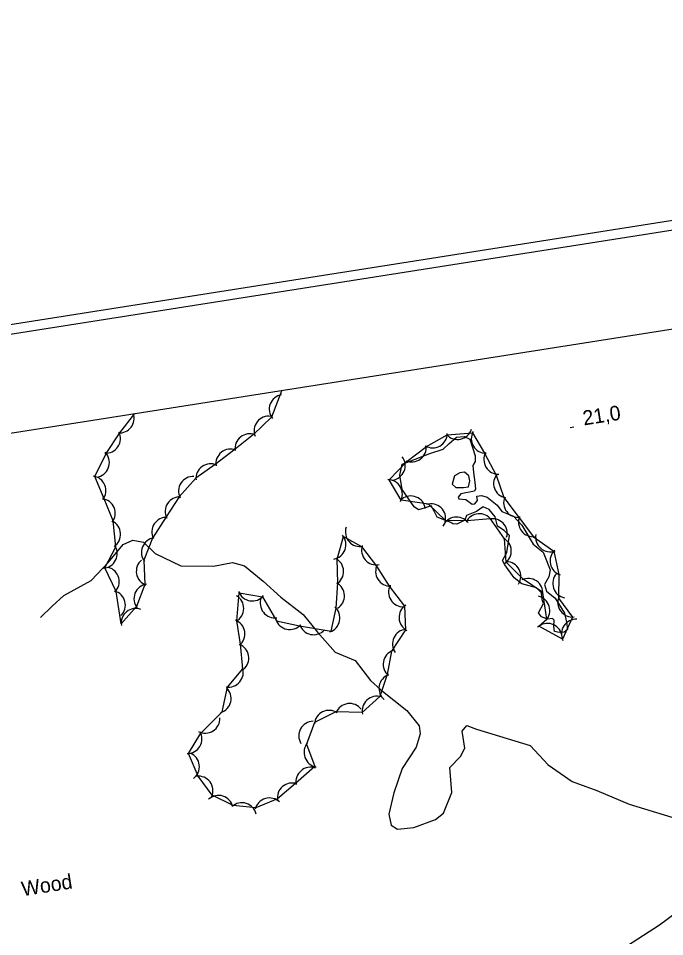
# Model space of a CAD drawing. Extents: x 646142 to 649934, y 5874075 to 5876351.
# Drawn here: x 646416.2 to 646548.7, y 5875715 to 5875903.2 of the extents above; entities that cross this region are included whole.
import ezdxf

# ---------------------------------------------------------------- set-up
doc = ezdxf.new("R2010")
doc.units = 0
for name, color, linetype in [('Niveau 1', 7, 'Continuous'), ('Niveau 3', 7, 'Continuous'), ('Niveau 4', 7, 'Continuous'), ('Niveau 44', 7, 'Continuous'), ('Niveau 60', 7, 'Continuous')]:
    doc.layers.add(name, color=color, linetype=linetype)

msp = doc.modelspace()

# ---------------------------------------------------------------- linework, layer by layer
at = {"layer": 'Niveau 1'}
for points in [[(646420.73, 5875780.37), (646423.1, 5875782.75), (646425.52, 5875784.92), (646431.11, 5875787.96), (646434.68, 5875791.71), (646437.69, 5875795.35), (646439.62, 5875796.25), (646441.82, 5875795.84), (646444.26, 5875793.49), (646449.51, 5875790.96), (646456.16, 5875790.91), (646460.09, 5875791.68), (646462.56, 5875791.01), (646466.38, 5875787.81), (646470.02, 5875784.59), (646474.59, 5875781), (646477.53, 5875777.36), (646481.17, 5875773.27), (646485.27, 5875771.61), (646488.37, 5875767.51), (646490.52, 5875765.6), (646495.86, 5875761.36), (646498.38, 5875758.21), (646498.57, 5875756.53), (646497.72, 5875753.8), (646494.84, 5875749.43), (646493.14, 5875744.44), (646492.17, 5875740.11), (646492.61, 5875737.83), (646493.94, 5875736.99), (646497.28, 5875737.32), (646501.7, 5875739.01), (646503.36, 5875740.31), (646505.09, 5875744.55), (646504.62, 5875749.64), (646506.82, 5875751.88), (646507.73, 5875753.63), (646507.2, 5875757.13), (646508.13, 5875758.24), (646510.14, 5875757.48), (646514.8, 5875756.09), (646521.15, 5875754.14), (646524.81, 5875750.19), (646529.7, 5875746.78), (646534.81, 5875744.93), (646541.43, 5875742.14), (646550.14, 5875739.47)], [(646552.87, 5875721.22), (646547.65, 5875717.34), (646541.08, 5875713.12)]]:
    msp.add_lwpolyline(points, dxfattribs=at)
at = {"layer": 'Niveau 3'}
msp.add_line((646529.29, 5875819.34), (646530.08, 5875819.46), dxfattribs=at)
at = {"layer": 'Niveau 4'}
for points in [[(646504.86, 5875799.87), (646503.64, 5875800.31), (646502.05, 5875800.95), (646501.44, 5875802.16), (646500.85, 5875803.26), (646499.61, 5875802.89), (646498.25, 5875802.49), (646497.36, 5875803.09), (646494.85, 5875806.66), (646494.4, 5875809.54), (646494.84, 5875811.82), (646496.3, 5875812.34), (646500.55, 5875814), (646503.25, 5875814.9), (646504.41, 5875815.98), (646506.01, 5875817.33), (646507.62, 5875817.52), (646508.74, 5875816.95), (646509.83, 5875813.56), (646509.84, 5875812.39), (646509.36, 5875811.52), (646509.52, 5875810.13), (646509.76, 5875808.05), (646509.91, 5875806.78), (646509.73, 5875806.29), (646506.87, 5875805.72), (646506.36, 5875805.08), (646506.52, 5875804.74), (646507.94, 5875804.56), (646509.21, 5875803.65), (646509.79, 5875803.72), (646510.3, 5875804.37), (646510.19, 5875805.29), (646511.12, 5875805.4), (646512.32, 5875805.07), (646514.38, 5875803.43), (646515.34, 5875802.14), (646517.68, 5875801.13), (646519.4, 5875799.34)], [(646505.91, 5875807.02), (646507.42, 5875807.07), (646508.46, 5875807.19), (646508.78, 5875808.4), (646508.55, 5875809.43), (646507.65, 5875810.15), (646506.73, 5875810.04), (646505.63, 5875809.44), (646505.12, 5875807.74), (646505.91, 5875807.02)], [(646519.4, 5875799.34), (646521.72, 5875795.39), (646523.78, 5875793.76), (646525.24, 5875790.19), (646524.94, 5875788.75), (646524.07, 5875787.13), (646524.46, 5875785.77), (646526.26, 5875784.34), (646528.13, 5875781.28), (646528.57, 5875779.46), (646528.74, 5875777.96), (646528.1, 5875777.42), (646527.07, 5875777.3), (646526.11, 5875777.54), (646525.99, 5875778.58), (646526.07, 5875779.87), (646525.69, 5875780.18), (646524.65, 5875780.06), (646523.43, 5875780.5), (646522.86, 5875781.37), (646523.82, 5875783.24), (646523.61, 5875784.03), (646523.45, 5875785.42), (646522.4, 5875786.46), (646519.38, 5875787.28), (646517.84, 5875788.51), (646515.9, 5875791.2), (646515.45, 5875792.09), (646516.31, 5875793.71), (646516.85, 5875797.17), (646515.79, 5875798.21), (646514.41, 5875799.11), (646513.95, 5875801.04), (646512.73, 5875802.54), (646511.5, 5875803.1), (646510.09, 5875802.12), (646508.08, 5875801.3), (646507.73, 5875800.32), (646506.07, 5875799.54), (646505.25, 5875799.56), (646504.86, 5875799.87)]]:
    msp.add_lwpolyline(points, dxfattribs=at)
at = {"layer": 'Niveau 44'}
for points in [[(646470.23, 5875826.96), (646468.1, 5875821.45), (646464.39, 5875817.93), (646460.6, 5875814.9), (646456.55, 5875811.75), (646452.6, 5875808.93), (646449.13, 5875805.11), (646446.48, 5875801.05), (646443.68, 5875796.67), (646441.88, 5875792.16), (646442.13, 5875787.16), (646440.37, 5875782.64), (646437.26, 5875779.08), (646436.21, 5875785.71), (646433.92, 5875790.54), (646436.16, 5875794.85), (646435.59, 5875800.2), (646433.75, 5875804.69), (646431.85, 5875809.31), (646434.18, 5875814.04), (646437.02, 5875818.23), (646440.03, 5875822.21)], [(646524.53, 5875780.02), (646523.72, 5875785.49), (646519.71, 5875788.23), (646516.18, 5875791.71), (646515.84, 5875796.55), (646512.97, 5875800.64), (646508.13, 5875800.21), (646503.76, 5875800.3), (646500.24, 5875803.64), (646494.65, 5875804.42), (646492.24, 5875808.63), (646495.91, 5875812.42), (646499.87, 5875815.44), (646504.1, 5875817.8), (646509.28, 5875818.22), (646511.78, 5875814.06), (646514.16, 5875809.58), (646515.75, 5875805), (646518.85, 5875800.81), (646521.82, 5875796.96), (646525.94, 5875793.97), (646527, 5875789.24), (646526.93, 5875784.38), (646529.83, 5875780.49), (646527.72, 5875775.98), (646522.89, 5875778.6), (646524.53, 5875780.02)], [(646475.25, 5875754.41), (646476.94, 5875749.85), (646472.99, 5875746.39), (646469.29, 5875743.24), (646464.84, 5875741.41), (646460.21, 5875741.84), (646455.95, 5875744.01), (646453.02, 5875747.88), (646451.08, 5875752.55), (646453.59, 5875756.7), (646457.99, 5875761.03), (646459.08, 5875766.13), (646462.2, 5875769.85), (646461.76, 5875774.92), (646460.98, 5875779.71), (646461.46, 5875785.43), (646466.25, 5875784.65), (646469.09, 5875779.7), (646473.83, 5875778.69), (646480.35, 5875777.56), (646481.31, 5875782.32), (646481.71, 5875787.48), (646481.55, 5875792.33), (646482.82, 5875796.99), (646486.52, 5875794.95), (646489.64, 5875790.93), (646492.23, 5875786.82), (646495.35, 5875782.73), (646495.59, 5875777.88), (646492.66, 5875773.48), (646491.82, 5875768.7), (646490.27, 5875764.19), (646486.69, 5875760.92), (646481.28, 5875761.03), (646476.92, 5875758.89), (646475.25, 5875754.41)]]:
    msp.add_lwpolyline(points, dxfattribs=at)
for centre, start, end in [((646470.62, 5875823.07), 98.8542, 218.8322), ((646436.92, 5875821.23), 265.9421, 18.3245), ((646467.5, 5875818.65), 81.7003, 201.6783), ((646434.12, 5875817.08), 265.9421, 25.9201), ((646463.59, 5875815.04), 68.5673, 188.5452), ((646501.13, 5875818.16), 239.1753, 359.1533), ((646506.23, 5875819.89), 222.1959, 342.1739), ((646512.04, 5875817.05), 151.0539, 271.0319), ((646496.82, 5875815.28), 246.3383, 6.3162), ((646431.85, 5875812.15), 285.0724, 45.0503), ((646459.68, 5875811.92), 68.5673, 188.5452), ((646514.62, 5875812.76), 151.0539, 271.0319), ((646455.6, 5875808.9), 65.5102, 185.4882), ((646492.5, 5875811.51), 277.9245, 37.9024), ((646516.62, 5875807.87), 139.0761, 259.0541), ((646431.14, 5875806.4), 322.3551, 82.333), ((646452.02, 5875806.3), 86.8929, 206.8709), ((646491.92, 5875805.65), 329.7554, 89.7333), ((646433.04, 5875801.77), 322.3551, 82.333), ((646449.28, 5875802.12), 86.8929, 206.8709), ((646496.65, 5875802.3), 8.0684, 128.0463), ((646518.68, 5875803.92), 157.6441, 277.6221), ((646500.79, 5875800.69), 346.5846, 106.5626), ((646446.55, 5875797.93), 86.8929, 206.8709), ((646506.03, 5875797.99), 38.5043, 158.4822), ((646510.71, 5875798.67), 35.0939, 155.0718), ((646513.41, 5875797.63), 344.4202, 104.3982), ((646521.73, 5875799.96), 157.6441, 277.6221), ((646434.14, 5875797.45), 303.9897, 63.9676), ((646486.23, 5875797.93), 161.5597, 281.5376), ((646444.42, 5875793.76), 98.2442, 218.2222), ((646480.34, 5875795.31), 280.0978, 40.0758), ((646514.25, 5875794.01), 303.918, 63.8959), ((646525.24, 5875796.86), 169.5257, 289.5036), ((646433.47, 5875793.51), 272.4811, 32.459), ((646489.55, 5875794.19), 161.5597, 281.5376), ((646528.19, 5875791.99), 132.6668, 252.6447), ((646443.36, 5875789.86), 130.0043, 249.9823), ((646479.87, 5875789.84), 301.98, 61.9579), ((646492.43, 5875789.82), 152.2091, 272.187), ((646516.2, 5875788.83), 328.345, 88.3229), ((646433.86, 5875787.76), 314.545, 74.523), ((646528.75, 5875787.37), 138.1902, 258.1681), ((646442.89, 5875784.26), 98.7344, 218.7123), ((646480.04, 5875784.84), 301.98, 61.9579), ((646520.72, 5875785.4), 355.5958, 115.5737), ((646435.12, 5875782.92), 314.545, 74.523), ((646464.14, 5875786.78), 200.6953, 320.6732), ((646495.09, 5875785.59), 152.2091, 272.187), ((646459.39, 5875782.26), 299.3328, 59.3108), ((646468.77, 5875783.32), 158.293, 278.2709), ((646522.14, 5875781.84), 316.7725, 76.7505), ((646529.79, 5875783.48), 156.6071, 276.5851), ((646440.26, 5875779.25), 69.1719, 189.1499), ((646479.1, 5875780.29), 288.5829, 48.5608), ((646497.23, 5875780.39), 122.7872, 242.7651), ((646459.63, 5875777.03), 309.3064, 69.2843), ((646471.83, 5875780.92), 197.8973, 317.8752), ((646530.53, 5875777.03), 86.4318, 206.4098), ((646476.72, 5875779.87), 197.8973, 317.8752), ((646495.89, 5875774.97), 95.1109, 215.0888), ((646524.67, 5875776.18), 12.4706, 132.4485), ((646460.44, 5875772.09), 309.3064, 69.2843), ((646493.98, 5875770.79), 110.1251, 230.103), ((646459.29, 5875769.13), 259.9612, 19.9391), ((646493.12, 5875765.86), 110.1251, 230.103), ((646456.8, 5875763.78), 287.4473, 47.4253), ((646484.11, 5875759.76), 37.7236, 157.7015), ((646489.67, 5875761.25), 72.4023, 192.3803), ((646479.88, 5875758.37), 56.1407, 176.1186), ((646454.52, 5875759.7), 241.9011, 1.879), ((646476.68, 5875756.14), 91.4556, 211.4335), ((646450.83, 5875755.53), 268.9382, 28.9161), ((646477.75, 5875752.74), 140.2746, 260.2526), ((646450.3, 5875749.82), 306.6382, 66.6162), ((646476.09, 5875746.71), 70.3872, 190.3651), ((646453.08, 5875744.88), 337.0059, 96.9839), ((646472.28, 5875743.47), 70.3872, 190.3651), ((646457.23, 5875740.92), 12.7008, 132.6787), ((646462.01, 5875739.43), 12.7008, 132.6787), ((646467.67, 5875740.41), 46.3598, 166.3378)]:
    msp.add_arc(centre, 3, start, end, dxfattribs=at)
at = {"layer": 'Niveau 60'}
for points in [[(646142.26, 5875797.64), (649662.59, 5876351.49), (649933.58, 5874629.01), (646413.32, 5874074.83), (646142.26, 5875797.64)], [(646144.55, 5875795.97), (649660.92, 5876349.21), (649931.28, 5874630.65), (646414.98, 5874077.12), (646144.55, 5875795.97)]]:
    msp.add_lwpolyline(points, dxfattribs=at)
msp.add_lwpolyline([(646167.42, 5875779.32), (649130.97, 5876245.57), (649395.18, 5874566.24), (646431.63, 5874099.99)], close=True, dxfattribs=at)
msp.add_lwpolyline([(646167.42, 5875779.32), (649130.97, 5876245.57), (649395.18, 5874566.24), (646431.63, 5874099.99)], close=True, dxfattribs=at)

# ---------------------------------------------------------------- texts
at = {"layer": 'Niveau 3'}
msp.add_text('21,0 ', height=3, rotation=8.941, dxfattribs=at).set_placement((646532.14, 5875819.75))
at = {"layer": 'Niveau 44'}
msp.add_text('Wood', height=3, rotation=8.9405, dxfattribs=at).set_placement((646417.07, 5875723.26))

doc.saveas('drawing.dxf')
